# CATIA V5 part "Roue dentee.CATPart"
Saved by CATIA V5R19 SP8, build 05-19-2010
Part number: Pignon
Bounding box of the stored display mesh (mm): x 0 to 8, y -27 to 27, z -27 to 27
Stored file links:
  D:\Mes documents\2020 TSTI2D\2I2D\SERRE\EE\CATIA\Roue dentee.CATPart
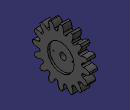
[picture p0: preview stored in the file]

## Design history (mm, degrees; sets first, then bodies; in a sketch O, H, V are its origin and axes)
Body1 (main body)
  Sketch1 on yz-plane, origin (0, 0, 0), H (0, 1, 0), V (0, 0, 1)
    construction line L1 (0, 0) -> (0, -93.6452)
    construction line L2 (0, 0) -> (4.0733, -110.0373)
    construction line L3 (0, 0) -> (10.6706, -108.2436)
    axis line L4 (0, 0) -> (12.8445, -113.0854)
    point P5 (0.9988, -26.9815)
    point P6 (0, -27)
    spline S1 through (2.2853, -20.1206) (2.5449, -22.4059) (2.3545, -23.8842) (0.9988, -26.9815)
    arc A1 centre (0, 0) radius 20.25 from (2.2853, -20.1206) to (3.9506, -19.8609) ccw
    line L5 (0, 0) -> (3.9506, -19.8609)
    point P7 (3.9506, -19.8609)
    point P8 (2.2853, -20.1206)
    point P9 (0, 0)
    construction line L6 through (0, 0) direction (-1, 0)
    point P10 (-0.9988, -26.9815)
    point P11 (0, -27)
    point P12 (-3.9506, -19.8609)
    point P13 (-2.2853, -20.1206)
    spline S2 through (-2.2853, -20.1206) (-2.5449, -22.4059) (-2.3545, -23.8842) (-0.9988, -26.9815)
    arc A2 centre (0, 0) radius 20.25 from (-2.2853, -20.1206) to (-3.9506, -19.8609) cw
    line L7 (0, 0) -> (-3.9506, -19.8609)
    arc A3 centre (0, 0) radius 27 from (-0.9988, -26.9815) to (0.9988, -26.9815) ccw
    point P14 (-0.9988, -26.9815)
    point P15 (0.9988, -26.9815)
    point P16 (2.2853, -20.1206)
    point P17 (2.5449, -22.4059)
    point P18 (2.3545, -23.8842)
    point P19 (0.9988, -26.9815)
    point P20 (-0.9988, -26.9815)
    point P21 (-2.2853, -20.1206)
    point P22 (-2.3545, -23.8842)
    point P23 (-2.5449, -22.4059)
    angle L2 L1 = 2.12
    angle L3 L1 = 5.63
    angle L4 L1 = 6.48
    distance P17 O = 22.55
    distance P18 O = 24
    radius A1 = 20.25
    angle L1 L5 = 11.25
    radius A3 = 27
    vertical: L1 V
    coincidence: P5 L2, P6 L1, P17 L4, P18 L3, P19 P5, P16 A1, P16 P8, P8 L4, O P9, P6 P11, P10 P20, P13 P21, S2 P14, S1 P15, P15 P19
    symmetry: H L6 L1, P5 P10 L1, P6 P11 L1, P7 P12 L1, P8 P13 L1, S1 S2 L1, A1 A2 L1, L5 L7 L1, P19 P20 L1, P16 P21 L1, P18 P22 L1, P17 P23 L1
  Pad1: profile Sketch1, direction (1, 0, 0), length 8
  Fillet1: radius 1.6, on edge [face of Pad1 from Sketch1.A1 | face of Pad1 from Sketch1.S1]; edge [face of Pad1 from Sketch1.S2 | face of Pad1 from Sketch1.A2]
  CircPattern1: of Pad1, Fillet1, instances 16, angular step 22.5, axis from edge [face of Pad1 from Sketch1.L7 | face of Pad1 from Sketch1.L5]
  Sketch2 on face of CircPattern1, origin (8, 12.5494, 3.5455), H (0, 1, 0), V (0, 0, 1)
    point P1 (-12.5494, -3.5455)
    reference projected arc E1 centre (-12.5494, -3.5455) radius 27 from (12.7605, 5.8572) to (11.996, 7.7027) ccw from edge [face of CircPattern1 | face of CircPattern1]
    concentricity: E1 P1
  Hole1: placed by Sketch2, at (8, 0, 0) direction (-1, 0, 0), diameter 6, through (limit type 6)
  Sketch3 on face of CircPattern1, origin (8, 0, 0), H (0, 1, 0), V (0, 0, 1)
    circle A1 centre (0, 0) radius 12.5
    radius A1 = 12.5
  Pocket1: profile Sketch3, direction (-1, 0, 0), length 2
  Sketch4 on end face of Pocket1, origin (6, 0, 0), H (0, 1, 0), V (0, 0, 1)
    circle A1 centre (-9, 0) radius 0.5
    point P1 (-9, 0)
    circle A2 centre (9, 0) radius 0.5
    point P2 (9, 0)
    radius A2 = 0.5
    radius A1 = 0.5
    distance P1 P2 = 18
    coincidence: P1 H, P2 H
    symmetry: P1 P2 V
  Pocket2: profile Sketch4, direction (-1, 0, 0), through (limit type 6)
